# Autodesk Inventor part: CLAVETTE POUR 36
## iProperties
Created: 2004-11
Part Number: CLAVETTE POUR 36
Document SubType Name: Modeling
Designer: Bruno
Manufacturer: Standard
Standards Organization: Custom
Author: Bruno
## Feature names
1. Base1
